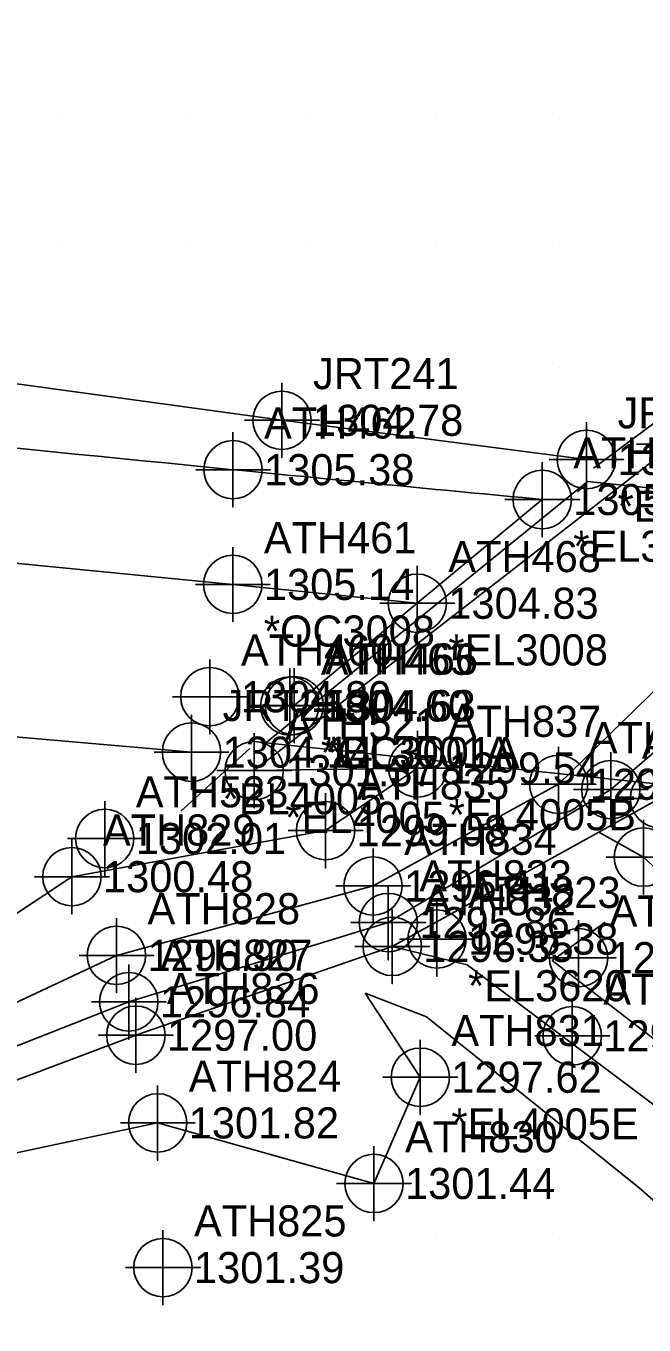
# Model space of a CAD drawing. Extents: x 1234484 to 1235382, y 695050 to 695510.
# Drawn here: x 1234887.1 to 1234936.8, y 695263.1 to 695367.4 of the extents above; entities that cross this region are included whole.
import ezdxf

# ---------------------------------------------------------------- set-up
doc = ezdxf.new("R2010")
doc.units = 0
for name, color, linetype in [('Exist DTM Breakline', 7, 'Continuous'), ('Exist DTM Breakline Cogo Comment', 7, 'Continuous'), ('Exist DTM Breakline Cogo Elevation', 7, 'Continuous'), ('Exist DTM Breakline Cogo Number', 7, 'Continuous'), ('Exist DTM Breakline Cogo Point CELL', 7, 'Continuous'), ('Exist DTM Breakline Underwater', 7, 'Continuous'), ('Exist DTM Crownline', 7, 'Continuous'), ('Exist DTM Crownline Cogo Comment', 7, 'Continuous'), ('Exist DTM Crownline Cogo Elevation', 7, 'Continuous'), ('Exist DTM Crownline Cogo Number', 7, 'Continuous'), ('Exist DTM Crownline Cogo Point CELL', 7, 'Continuous'), ('Exist DTM Drainline Cogo Elevation', 7, 'Continuous'), ('Exist DTM Drainline Cogo Number', 7, 'Continuous'), ('Exist DTM Drainline Cogo Point CELL', 7, 'Continuous'), ('Exist DTM QL2 LIDAR Elevation Point', 7, 'Continuous'), ('Exist DTM Regular Point CELL', 7, 'Continuous'), ('Exist DTM Regular Point Cogo Elevation', 7, 'Continuous'), ('Exist DTM Regular Point Cogo Number', 7, 'Continuous'), ('Exist DTM Regular Point Underwater CELL', 7, 'Continuous'), ('Exist DTM Regular Point Underwater Cogo Elevation', 7, 'Continuous'), ('Exist DTM Regular Point Underwater Cogo Number', 7, 'Continuous'), ('Exist Hydro Stream or Body of Water', 7, 'Continuous'), ('Exist Hydro Stream or Body of Water Cogo Comment', 7, 'Continuous'), ('Exist Hydro Stream or Body of Water Cogo Elevation', 7, 'Continuous'), ('Exist Hydro Stream or Body of Water Cogo Number', 7, 'Continuous'), ('Exist Hydro Stream or Body of Water Cogo Point CELL', 7, 'Continuous'), ('Exist Roads EOP', 7, 'Continuous'), ('Exist Roads EOP Cogo Comment', 7, 'Continuous'), ('Exist Roads EOP Cogo Elevation', 7, 'Continuous'), ('Exist Roads EOP Cogo Number', 7, 'Continuous'), ('Exist Roads EOP Cogo Point CELL', 7, 'Continuous'), ('Exist Structure Major Deck Tunnel Box Culvert', 7, 'Continuous')]:
    doc.layers.add(name, color=color, linetype=linetype)

msp = doc.modelspace()

# ---------------------------------------------------------------- linework, layer by layer
at = {"layer": 'Exist DTM Breakline'}
for p, q in [((1234932.724, 695331.913), (1234938.803, 695336.41)), ((1234939.196, 695333.825), (1234905.457, 695307.608)), ((1234932.724, 695331.913), (1234932.724, 695331.913)), ((1234905.117, 695309.399), (1234899.57, 695304.354)), ((1234918.594, 695307.818), (1234905.457, 695307.608)), ((1234918.81, 695282.981), (1234914.388, 695289.733))]:
    msp.add_line(p, q, dxfattribs=at)
for points in [[(1234608.156, 695366.132), (1234620.219, 695363.657), (1234657.83, 695357.954), (1234716.822, 695351.015), (1234771.134, 695347.284), (1234823.515, 695343.018), (1234867.598, 695341.251), (1234907.686, 695335.753), (1234932.171, 695332.602)], [(1234900.418, 695309.093), (1234843.128, 695314.065), (1234821.486, 695313.61), (1234768.142, 695320.476), (1234713.4, 695324.265), (1234656.708, 695330.451), (1234602.942, 695334.287)], [(1234766.2, 695216.412), (1234807.252, 695252.276), (1234839.673, 695274.467), (1234869.326, 695284.86), (1234890.801, 695299.09), (1234911.196, 695302.79), (1234918.594, 695307.818)], [(1234933.683, 695295.436), (1234929.419, 695292.356), (1234942.895, 695281.98), (1234955.338, 695274.07), (1234960.662, 695260.925), (1234955.311, 695244.507), (1234951.042, 695246.761), (1234943.062, 695238.239), (1234919.786, 695222.886), (1234917.573, 695214.076), (1234899.933, 695199.243), (1234885.657, 695179.089)], [(1234882.128, 695182.331), (1234896.107, 695201.799), (1234912.336, 695216.249), (1234916.953, 695226.235), (1234940.483, 695242.348), (1234951.207, 695257.798), (1234946.446, 695265.278), (1234936.421, 695274.091), (1234919.314, 695287.826), (1234914.388, 695289.733)], [(1234840.371, 695218.638), (1234853.212, 695244.202), (1234858.487, 695270.963), (1234871.461, 695273.745), (1234897.697, 695279.312), (1234915.088, 695274.445), (1234918.81, 695282.981)]]:
    msp.add_lwpolyline(points, dxfattribs=at)
at = {"layer": 'Exist DTM Breakline Cogo Point CELL'}
for points in [[(1234907.686, 695338.753), (1234907.686, 695332.753), (1234907.686, 695335.753), (1234910.686, 695335.753), (1234904.686, 695335.753)], [(1234939.196, 695336.825), (1234939.196, 695330.825), (1234939.196, 695333.825), (1234942.196, 695333.825), (1234936.196, 695333.825)], [(1234932.171, 695335.602), (1234932.171, 695329.602), (1234932.171, 695332.602), (1234935.171, 695332.602), (1234929.171, 695332.602)], [(1234900.418, 695312.093), (1234900.418, 695306.093), (1234900.418, 695309.093), (1234903.418, 695309.093), (1234897.418, 695309.093)], [(1234905.457, 695310.608), (1234905.457, 695304.608), (1234905.457, 695307.608), (1234908.457, 695307.608), (1234902.457, 695307.608)], [(1234918.594, 695310.818), (1234918.594, 695304.818), (1234918.594, 695307.818), (1234921.594, 695307.818), (1234915.594, 695307.818)], [(1234911.196, 695305.79), (1234911.196, 695299.79), (1234911.196, 695302.79), (1234914.196, 695302.79), (1234908.196, 695302.79)], [(1234890.801, 695302.09), (1234890.801, 695296.09), (1234890.801, 695299.09), (1234893.801, 695299.09), (1234887.801, 695299.09)], [(1234918.81, 695285.981), (1234918.81, 695279.981), (1234918.81, 695282.981), (1234921.81, 695282.981), (1234915.81, 695282.981)], [(1234897.697, 695282.312), (1234897.697, 695276.312), (1234897.697, 695279.312), (1234900.697, 695279.312), (1234894.697, 695279.312)], [(1234915.088, 695277.445), (1234915.088, 695271.445), (1234915.088, 695274.445), (1234918.088, 695274.445), (1234912.088, 695274.445)]]:
    msp.add_lwpolyline(points, dxfattribs=at)
for centre in [(1234907.686, 695335.753), (1234932.171, 695332.602), (1234900.418, 695309.093), (1234905.457, 695307.608), (1234918.594, 695307.818), (1234911.196, 695302.79), (1234890.801, 695299.09), (1234918.81, 695282.981), (1234897.697, 695279.312), (1234915.088, 695274.445)]:
    msp.add_circle(centre, 2.344, dxfattribs=at)
at = {"layer": 'Exist DTM Breakline Underwater'}
msp.add_line((1234936.748, 695300.66), (1234933.154, 695302.663), dxfattribs=at)
msp.add_lwpolyline([(1234766.421, 695209.389), (1234812.885, 695247.237), (1234843.411, 695272.621), (1234869.986, 695279.055), (1234895.378, 695289.036), (1234916.238, 695295.408), (1234934.131, 695306.081), (1234961.466, 695329.617), (1234991.436, 695342.664), (1235009.265, 695346.147), (1235040.352, 695365.623), (1235072.367, 695380.008), (1235092.174, 695396.335)], dxfattribs=at)
at = {"layer": 'Exist DTM Crownline'}
msp.add_line((1234903.738, 695322.57), (1234918.568, 695321.057), dxfattribs=at)
msp.add_lwpolyline([(1234511.603, 695359.057), (1234605.73, 695349.422), (1234657.657, 695344.297), (1234715.146, 695339.445), (1234769.335, 695334.825), (1234822.546, 695330.321), (1234845.176, 695328.304), (1234903.738, 695322.57)], dxfattribs=at)
at = {"layer": 'Exist DTM Crownline Cogo Point CELL'}
for points in [[(1234903.738, 695325.57), (1234903.738, 695319.57), (1234903.738, 695322.57), (1234906.738, 695322.57), (1234900.738, 695322.57)], [(1234918.568, 695324.057), (1234918.568, 695318.057), (1234918.568, 695321.057), (1234921.568, 695321.057), (1234915.568, 695321.057)], [(1234936.748, 695303.66), (1234936.748, 695297.66), (1234936.748, 695300.66), (1234939.748, 695300.66), (1234933.748, 695300.66)]]:
    msp.add_lwpolyline(points, dxfattribs=at)
for centre in [(1234903.738, 695322.57), (1234918.568, 695321.057), (1234936.748, 695300.66)]:
    msp.add_circle(centre, 2.344, dxfattribs=at)
at = {"layer": 'Exist DTM Drainline Cogo Point CELL'}
for points in [[(1234929.933, 695309.511), (1234929.933, 695303.511), (1234929.933, 695306.511), (1234932.933, 695306.511), (1234926.933, 695306.511)], [(1234938.044, 695308.366), (1234938.044, 695302.366), (1234938.044, 695305.366), (1234941.044, 695305.366), (1234935.044, 695305.366)], [(1234915.014, 695301.345), (1234915.014, 695295.345), (1234915.014, 695298.345), (1234918.014, 695298.345), (1234912.014, 695298.345)], [(1234916.555, 695296.487), (1234916.555, 695290.487), (1234916.555, 695293.487), (1234919.555, 695293.487), (1234913.555, 695293.487)], [(1234894.384, 695295.767), (1234894.384, 695289.767), (1234894.384, 695292.767), (1234897.384, 695292.767), (1234891.384, 695292.767)], [(1234895.944, 695289.356), (1234895.944, 695283.356), (1234895.944, 695286.356), (1234898.944, 695286.356), (1234892.944, 695286.356)]]:
    msp.add_lwpolyline(points, dxfattribs=at)
for centre in [(1234929.933, 695306.511), (1234938.044, 695305.366), (1234915.014, 695298.345), (1234894.384, 695292.767), (1234916.555, 695293.487), (1234895.944, 695286.356)]:
    msp.add_circle(centre, 2.344, dxfattribs=at)
at = {"layer": 'Exist DTM QL2 LIDAR Elevation Point'}
for p, q in [((1234890, 695360), (1234890, 695360)), ((1234900, 695360), (1234900, 695360)), ((1234910, 695360), (1234910, 695360)), ((1234920, 695360), (1234920, 695360)), ((1234930, 695360), (1234930, 695360)), ((1234890, 695350), (1234890, 695350)), ((1234900, 695350), (1234900, 695350)), ((1234910, 695350), (1234910, 695350)), ((1234920, 695350), (1234920, 695350)), ((1234930, 695350), (1234930, 695350)), ((1234930, 695340), (1234930, 695340)), ((1234920, 695270), (1234920, 695270)), ((1234930, 695270), (1234930, 695270))]:
    msp.add_line(p, q, dxfattribs=at)
at = {"layer": 'Exist DTM Regular Point CELL'}
for points in [[(1234893.441, 695305.158), (1234893.441, 695299.158), (1234893.441, 695302.158), (1234896.441, 695302.158), (1234890.441, 695302.158)], [(1234931.535, 695295.584), (1234931.535, 695289.584), (1234931.535, 695292.584), (1234934.535, 695292.584), (1234928.535, 695292.584)], [(1234898.118, 695270.687), (1234898.118, 695264.687), (1234898.118, 695267.687), (1234901.118, 695267.687), (1234895.118, 695267.687)]]:
    msp.add_lwpolyline(points, dxfattribs=at)
for centre in [(1234893.441, 695302.158), (1234931.535, 695292.584), (1234898.118, 695267.687)]:
    msp.add_circle(centre, 2.344, dxfattribs=at)
at = {"layer": 'Exist DTM Regular Point Underwater CELL'}
for points in [[(1234934.131, 695309.081), (1234934.131, 695303.081), (1234934.131, 695306.081), (1234937.131, 695306.081), (1234931.131, 695306.081)], [(1234916.238, 695298.408), (1234916.238, 695292.408), (1234916.238, 695295.408), (1234919.238, 695295.408), (1234913.238, 695295.408)], [(1234895.378, 695292.036), (1234895.378, 695286.036), (1234895.378, 695289.036), (1234898.378, 695289.036), (1234892.378, 695289.036)]]:
    msp.add_lwpolyline(points, dxfattribs=at)
for centre in [(1234934.131, 695306.081), (1234916.238, 695295.408), (1234895.378, 695289.036)]:
    msp.add_circle(centre, 2.344, dxfattribs=at)
at = {"layer": 'Exist Hydro Stream or Body of Water'}
for p, q in [((1234933.154, 695302.663), (1234938.044, 695305.366)), ((1234922.587, 695292.008), (1234916.555, 695293.487))]:
    msp.add_line(p, q, dxfattribs=at)
for points in [[(1234766.439, 695214.543), (1234809.451, 695250.146), (1234840.783, 695273.683), (1234870.231, 695281.467), (1234894.384, 695292.767), (1234915.014, 695298.345), (1234929.933, 695306.511), (1234953.845, 695329.807), (1234986.204, 695341.472), (1235008.526, 695348.915), (1235037.336, 695368.653), (1235069.491, 695383.302), (1235088.448, 695400.861)], [(1234770.872, 695207.044), (1234815.763, 695244.4), (1234847.025, 695270.849), (1234870.723, 695276.867), (1234895.944, 695286.356), (1234916.555, 695293.487), (1234933.154, 695302.663)], [(1234944.112, 695289.587), (1234945.266, 695292.782), (1234936.748, 695300.66), (1234933.154, 695302.663)], [(1234884.024, 695180.655), (1234897.944, 695200.742), (1234915.887, 695215.628), (1234918.027, 695224.801), (1234941.893, 695240.452), (1234957.27, 695259.086), (1234951.207, 695270.685), (1234942.31, 695277.234), (1234922.587, 695292.008)]]:
    msp.add_lwpolyline(points, dxfattribs=at)
at = {"layer": 'Exist Hydro Stream or Body of Water Cogo Point CELL'}
for points in [[(1234917.152, 695294.079), (1234923.152, 695294.079), (1234920.152, 695294.079), (1234920.152, 695291.079), (1234920.152, 695297.079)], [(1234928.024, 695286.305), (1234934.024, 695286.305), (1234931.024, 695286.305), (1234931.024, 695283.305), (1234931.024, 695289.305)]]:
    msp.add_lwpolyline(points, dxfattribs=at)
for centre in [(1234920.152, 695294.079), (1234931.024, 695286.305)]:
    msp.add_circle(centre, 2.344, dxfattribs=at)
at = {"layer": 'Exist Roads EOP'}
msp.add_line((1234908.315, 695312.805), (1234908.685, 695312.833), dxfattribs=at)
msp.add_lwpolyline([(1234908.685, 695312.833), (1234918.568, 695321.057), (1234928.613, 695329.389)], dxfattribs=at)
msp.add_spline([(1234605.599, 695398.165), (1234601.696, 695381.855), (1234613.593, 695357.692), (1234658.916, 695353.52), (1234716.264, 695348.291), (1234770.499, 695343.743), (1234823.09, 695339.258), (1234845.762, 695337.371), (1234903.754, 695331.785), (1234928.613, 695329.389)], degree=3, dxfattribs=at)
at = {"layer": 'Exist Roads EOP Cogo Point CELL'}
for points in [[(1234903.754, 695334.785), (1234903.754, 695328.785), (1234903.754, 695331.785), (1234906.754, 695331.785), (1234900.754, 695331.785)], [(1234928.613, 695332.389), (1234928.613, 695326.389), (1234928.613, 695329.389), (1234931.613, 695329.389), (1234925.613, 695329.389)], [(1234901.893, 695316.546), (1234901.893, 695310.546), (1234901.893, 695313.546), (1234904.893, 695313.546), (1234898.893, 695313.546)], [(1234908.315, 695315.805), (1234908.315, 695309.805), (1234908.315, 695312.805), (1234911.315, 695312.805), (1234905.315, 695312.805)], [(1234908.685, 695315.833), (1234908.685, 695309.833), (1234908.685, 695312.833), (1234911.685, 695312.833), (1234905.685, 695312.833)]]:
    msp.add_lwpolyline(points, dxfattribs=at)
for centre in [(1234903.754, 695331.785), (1234928.613, 695329.389), (1234901.893, 695313.546), (1234908.315, 695312.805), (1234908.685, 695312.833)]:
    msp.add_circle(centre, 2.344, dxfattribs=at)
at = {"layer": 'Exist Structure Major Deck Tunnel Box Culvert'}
msp.add_lwpolyline([(1234932.242, 695330.836), (1234906.381, 695309.848), (1234965.045, 695303.686), (1234990.33, 695324.837), (1234932.242, 695330.836)], dxfattribs=at)

# ---------------------------------------------------------------- texts
at = {"layer": 'Exist DTM Breakline Cogo Comment'}
for s, p in [('*EL4005', (1234934.671, 695327.602)), ('*BL4005', (1234902.918, 695304.093)), ('*EL4005B', (1234921.094, 695302.818)), ('*EL4005', (1234907.957, 695302.608)), ('*EL4005E', (1234921.31, 695277.981))]:
    msp.add_text(s, height=2.5, dxfattribs=at).set_placement(p)
at = {"layer": 'Exist DTM Breakline Cogo Elevation'}
for s, p in [('1304.78', (1234910.186, 695334.503)), ('1304.38', (1234934.671, 695331.352)), ('1304.14', (1234902.918, 695307.843)), ('1301.37', (1234907.957, 695306.358)), ('1299.54', (1234921.094, 695306.568)), ('1299.08', (1234913.696, 695301.54)), ('1300.48', (1234893.301, 695297.84)), ('1297.62', (1234921.31, 695281.731)), ('1301.82', (1234900.197, 695278.062)), ('1301.44', (1234917.588, 695273.195))]:
    msp.add_text(s, height=2.5, dxfattribs=at).set_placement(p)
at = {"layer": 'Exist DTM Breakline Cogo Number'}
for s, p in [('JRT241', (1234910.186, 695338.253)), ('JRT242', (1234934.671, 695335.102)), ('JRT258', (1234902.918, 695311.593)), ('ATH521', (1234907.957, 695310.108)), ('ATH837', (1234921.094, 695310.318)), ('ATH835', (1234913.696, 695305.29)), ('ATH829', (1234893.301, 695301.59)), ('ATH831', (1234921.31, 695285.481)), ('ATH824', (1234900.197, 695281.812)), ('ATH830', (1234917.588, 695276.945))]:
    msp.add_text(s, height=2.5, dxfattribs=at).set_placement(p)
at = {"layer": 'Exist DTM Crownline Cogo Comment'}
for s, p in [('*OC3008', (1234906.238, 695317.57)), ('*EL3008', (1234921.068, 695316.057))]:
    msp.add_text(s, height=2.5, dxfattribs=at).set_placement(p)
at = {"layer": 'Exist DTM Crownline Cogo Elevation'}
for s, p in [('1305.14', (1234906.238, 695321.32)), ('1304.83', (1234921.068, 695319.807))]:
    msp.add_text(s, height=2.5, dxfattribs=at).set_placement(p)
at = {"layer": 'Exist DTM Crownline Cogo Number'}
for s, p in [('ATH461', (1234906.238, 695325.07)), ('ATH468', (1234921.068, 695323.557))]:
    msp.add_text(s, height=2.5, dxfattribs=at).set_placement(p)
at = {"layer": 'Exist DTM Drainline Cogo Elevation'}
for s, p in [('1296.30', (1234932.433, 695305.261)), ('1296.41', (1234917.514, 695297.095)), ('1296.90', (1234896.884, 695291.517)), ('1296.35', (1234919.055, 695292.237)), ('1297.00', (1234898.444, 695285.106))]:
    msp.add_text(s, height=2.5, dxfattribs=at).set_placement(p)
at = {"layer": 'Exist DTM Drainline Cogo Number'}
for s, p in [('ATH838', (1234932.433, 695309.011)), ('ATH834', (1234917.514, 695300.845)), ('ATH832', (1234919.055, 695295.987)), ('ATH828', (1234896.884, 695295.267)), ('ATH826', (1234898.444, 695288.856))]:
    msp.add_text(s, height=2.5, dxfattribs=at).set_placement(p)
at = {"layer": 'Exist DTM Regular Point Cogo Elevation'}
for s, p in [('1302.01', (1234895.941, 695300.908)), ('1299.15', (1234934.035, 695291.334)), ('1301.39', (1234900.618, 695266.437))]:
    msp.add_text(s, height=2.5, dxfattribs=at).set_placement(p)
at = {"layer": 'Exist DTM Regular Point Cogo Number'}
for s, p in [('ATH523', (1234895.941, 695304.658)), ('ATH836', (1234934.035, 695295.084)), ('ATH825', (1234900.618, 695270.187))]:
    msp.add_text(s, height=2.5, dxfattribs=at).set_placement(p)
at = {"layer": 'Exist DTM Regular Point Underwater Cogo Elevation'}
for s, p in [('1295.86', (1234918.738, 695294.158)), ('1296.84', (1234897.878, 695287.786))]:
    msp.add_text(s, height=2.5, dxfattribs=at).set_placement(p)
at = {"layer": 'Exist DTM Regular Point Underwater Cogo Number'}
for s, p in [('ATH839', (1234936.631, 695308.581)), ('ATH833', (1234918.738, 695297.908)), ('ATH827', (1234897.878, 695291.536))]:
    msp.add_text(s, height=2.5, dxfattribs=at).set_placement(p)
at = {"layer": 'Exist Hydro Stream or Body of Water Cogo Comment'}
msp.add_text('*EL3620', height=2.5, dxfattribs=at).set_placement((1234922.652, 695289.079))
at = {"layer": 'Exist Hydro Stream or Body of Water Cogo Elevation'}
for s, p in [('1296.38', (1234922.652, 695292.829)), ('1296.90', (1234933.524, 695285.055))]:
    msp.add_text(s, height=2.5, dxfattribs=at).set_placement(p)
at = {"layer": 'Exist Hydro Stream or Body of Water Cogo Number'}
for s, p in [('ATH823', (1234922.652, 695296.579)), ('ATH822', (1234933.524, 695288.805))]:
    msp.add_text(s, height=2.5, dxfattribs=at).set_placement(p)
at = {"layer": 'Exist Roads EOP Cogo Comment'}
for s, p in [('*EL3001', (1234931.113, 695324.389)), ('*OC3001A', (1234910.815, 695307.805)), ('*EL3001A', (1234911.185, 695307.833))]:
    msp.add_text(s, height=2.5, dxfattribs=at).set_placement(p)
at = {"layer": 'Exist Roads EOP Cogo Elevation'}
for s, p in [('1305.38', (1234906.254, 695330.535)), ('1305.05', (1234931.113, 695328.139)), ('1304.80', (1234904.393, 695312.296)), ('1304.60', (1234910.815, 695311.555)), ('1304.63', (1234911.185, 695311.583))]:
    msp.add_text(s, height=2.5, dxfattribs=at).set_placement(p)
at = {"layer": 'Exist Roads EOP Cogo Number'}
for s, p in [('ATH462', (1234906.254, 695334.285)), ('ATH464', (1234931.113, 695331.889)), ('ATH460', (1234904.393, 695316.046)), ('ATH465', (1234910.815, 695315.305)), ('ATH466', (1234911.185, 695315.333))]:
    msp.add_text(s, height=2.5, dxfattribs=at).set_placement(p)

doc.saveas('drawing.dxf')
